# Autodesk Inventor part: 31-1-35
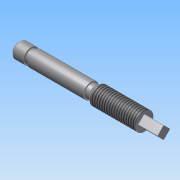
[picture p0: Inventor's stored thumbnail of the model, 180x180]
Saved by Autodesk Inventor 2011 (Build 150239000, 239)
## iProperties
Created: 2014-02
Part Number: 31-1-35
Document SubType Name: Modeling
Designer: Administrator
Density: 1 g/cm^3
Author: Administrator
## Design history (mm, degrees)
sketch "草图1"
  geometry: L1 (0, 8)-(11, 8); L2 (11, 8)-(11, 6.5); L3 (11, 6.5)-(15, 6.5); L4 (15, 6.5)-(15, 8); L5 (15, 8)-(73, 8); L6 (73, 8)-(73, 6.5); L7 (73, 6.5)-(77, 6.5); L8 (77, 6.5)-(81.096, 9.368); L9 (81.096, 9.368)-(128.096, 9.368); L10 (128.096, 9.368)-(128.096, 6.368); L11 (128.096, 6.368)-(148.096, 6.368); L12 (148.096, 6.368)-(148.096, 0); L13 (148.096, 0)-(0, 0); L14 (0, 0)-(-4, 0); A1 r 9.067 centre (5.055, 0.473) between (0, 8) and (-4, 0)
  constraints: 28 end point, 5 parallel, 3 perpendicular, 2 collinear, 2 point on circle, 1 centre point
  dimensions: "d0" = 8 distance of L13.end L1.start; "d1" = 11 distance of L1.start L1.end; "d2" = 1.5 distance of L1.end L2.end; "d3" = 4 distance of L2.end L3.end; "d4" = 1.5 distance of L3.end L4.end; "d5" = 58 distance of L4.end L5.end; "d6" = 1.5 distance of L5.end L6.end; "d7" = 4 distance of L6.end L7.end; "d8" = 5 distance of L7.end L8.end; "d9" = 145 deg angle of L8 L7; "d10" = 47 distance of L8.end L9.end; "d11" = 3 distance of L9.end L10.end; "d12" = 20 distance of L10.end L11.end
revolve "旋转1" sketch "草图1" stored, may be unused: angle "d14" = 90 deg
fillet "圆角1" dims "d15" = 1
feature "螺纹1" dims "d16" = 10, "d17" = 0
sketch "草图2"
  geometry: L1 (-6.358, 0.36)-(-0.36, 6.358); L2 (0.36, 6.358)-(6.358, 0.36); L3 (6.358, -0.36)-(0.36, -6.358); L4 (-0.36, -6.358)-(-6.358, -0.36); C1 r 6.368 at (0, 0) reference; A1 r 6.368 centre (0, 0) between (-0.36, 6.358) and (-6.358, 0.36); A2 r 6.368 centre (0, 0) between (-0.36, 6.358) and (-6.358, 0.36); A3 r 6.368 centre (0, 0) between (6.358, 0.36) and (0.36, 6.358); A4 r 6.368 centre (0, 0) between (6.358, 0.36) and (0.36, 6.358); A5 r 6.368 centre (0, 0) between (-6.358, -0.36) and (-0.36, -6.358); A6 r 6.368 centre (0, 0) between (0.36, -6.358) and (6.358, -0.36); A7 r 6.368 centre (0, 0) between (-6.358, -0.36) and (-0.36, -6.358); A8 r 6.368 centre (0, 0) between (0.36, -6.358) and (6.358, -0.36); 5 further points
  constraints: 16 point on circle, 8 centre point, 8 end point, 2 coincident, 2 horizontal alignment, 2 parallel, 2 vertical alignment, 1 perpendicular
  dimensions: "d24" = 9.5 distance of point (-6.718, 0) point (0, 6.718); "d25" = 9.5 distance of point (0, 6.718) point (6.718, 0) (derived)
extrude "拉伸1" cut sketch "草图2" stored distance "d26" = 10; taper "d27" = 0 deg
node "实体1"
node "投影回路1"
